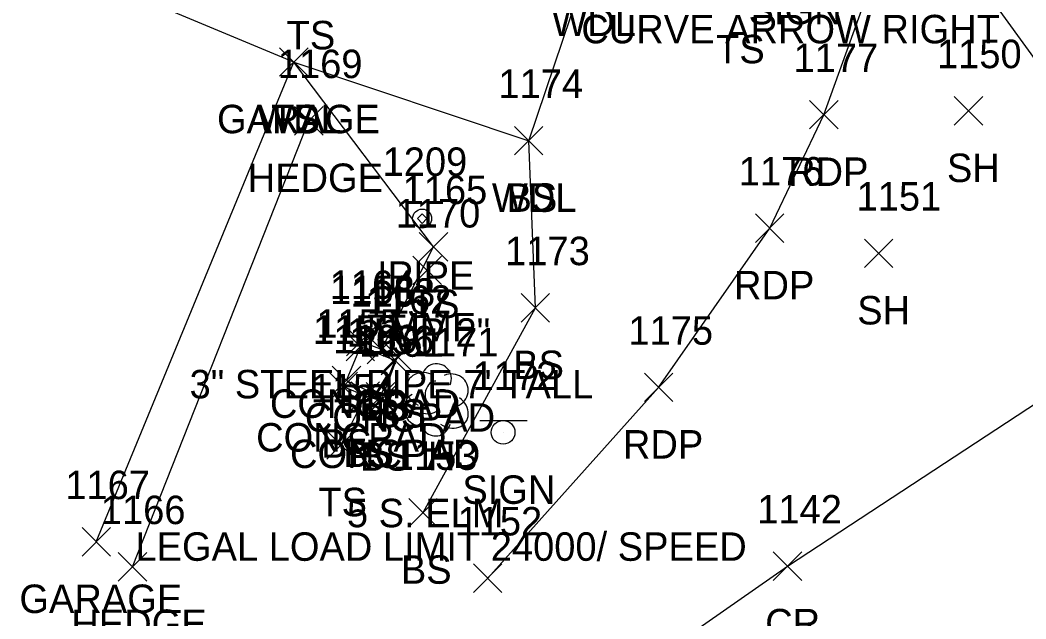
# Model space of a CAD drawing. Extents: x 1620157 to 1620595, y 115111 to 117885.
# Drawn here: x 1620292.5 to 1620363.2, y 115261.5 to 115303.5 of the extents above; entities that cross this region are included whole.
import ezdxf

# ---------------------------------------------------------------- set-up
doc = ezdxf.new("R2010")
doc.units = 0
for name, color, linetype in [('DCP', 7, 'Continuous'), ('L_A', 7, 'Continuous'), ('L_C', 7, 'Continuous'), ('L_I', 7, 'Continuous'), ('L_TIC', 7, 'Continuous'), ('LAHR', 7, 'Continuous'), ('LAWA', 7, 'Continuous'), ('LBC', 7, 'Continuous'), ('LELB', 7, 'Continuous'), ('LS', 7, 'Continuous'), ('LTD', 7, 'Continuous'), ('M_A', 7, 'Continuous'), ('M_C', 7, 'Continuous'), ('M_I', 7, 'Continuous'), ('MPIP', 7, 'Continuous'), ('P_A', 7, 'Continuous'), ('P_I', 7, 'Continuous'), ('P_TIC', 7, 'Continuous'), ('PET', 7, 'Continuous'), ('PRC', 7, 'Continuous'), ('S_A', 7, 'Continuous'), ('S_C', 7, 'Continuous'), ('S_I', 7, 'Continuous'), ('SSGN', 7, 'Continuous')]:
    doc.layers.add(name, color=color, linetype=linetype)

msp = doc.modelspace()

# ---------------------------------------------------------------- linework, layer by layer
at = {"layer": 'DCP'}
msp.add_lwpolyline([(1620401.963, 115248.346), (1620331.919, 115344.781)], dxfattribs=at)
at = {"layer": 'L_TIC'}
for points in [[(1620310.784, 115299.587), (1620312.784, 115301.587)], [(1620312.784, 115299.587), (1620310.784, 115301.587)], [(1620310.784, 115299.587), (1620312.784, 115301.587)], [(1620312.784, 115299.587), (1620310.784, 115301.587)], [(1620310.784, 115299.587), (1620312.784, 115301.587)], [(1620312.784, 115299.587), (1620310.784, 115301.587)], [(1620358.191, 115296.159), (1620360.191, 115298.159)], [(1620360.191, 115296.159), (1620358.191, 115298.159)], [(1620311.836, 115295.461), (1620313.836, 115297.461)], [(1620313.836, 115295.461), (1620311.836, 115297.461)], [(1620327.285, 115294.066), (1620329.285, 115296.066)], [(1620329.285, 115294.066), (1620327.285, 115296.066)], [(1620327.285, 115294.066), (1620329.285, 115296.066)], [(1620329.285, 115294.066), (1620327.285, 115296.066)], [(1620320.596, 115286.608), (1620322.596, 115288.608)], [(1620322.596, 115286.608), (1620320.596, 115288.608)], [(1620351.887, 115286.157), (1620353.887, 115288.157)], [(1620353.887, 115286.157), (1620351.887, 115288.157)], [(1620320.147, 115284.965), (1620322.147, 115286.965)], [(1620322.147, 115284.965), (1620320.147, 115286.965)], [(1620327.758, 115282.321), (1620329.758, 115284.321)], [(1620329.758, 115282.321), (1620327.758, 115284.321)], [(1620315.455, 115279.595), (1620317.455, 115281.595)], [(1620317.455, 115279.595), (1620315.455, 115281.595)], [(1620315.455, 115279.595), (1620317.455, 115281.595)], [(1620317.455, 115279.595), (1620315.455, 115281.595)], [(1620315.47, 115279.948), (1620317.47, 115281.948)], [(1620317.47, 115279.948), (1620315.47, 115281.948)], [(1620316.94, 115279.402), (1620318.94, 115281.402)], [(1620318.94, 115279.402), (1620316.94, 115281.402)], [(1620316.94, 115279.402), (1620318.94, 115281.402)], [(1620318.94, 115279.402), (1620316.94, 115281.402)], [(1620318.075, 115278.906), (1620320.075, 115280.906)], [(1620320.075, 115278.906), (1620318.075, 115280.906)], [(1620317.909, 115278.626), (1620319.909, 115280.626)], [(1620319.909, 115278.626), (1620317.909, 115280.626)], [(1620314.255, 115276.794), (1620316.255, 115278.794)], [(1620316.255, 115276.794), (1620314.255, 115278.794)], [(1620314.483, 115277.23), (1620316.483, 115279.23)], [(1620316.483, 115277.23), (1620314.483, 115279.23)], [(1620314.483, 115277.23), (1620316.483, 115279.23)], [(1620316.483, 115277.23), (1620314.483, 115279.23)], [(1620315.807, 115276.134), (1620317.807, 115278.134)], [(1620317.807, 115276.134), (1620315.807, 115278.134)], [(1620315.807, 115276.134), (1620317.807, 115278.134)], [(1620317.807, 115276.134), (1620315.807, 115278.134)], [(1620316.868, 115276.07), (1620318.868, 115278.07)], [(1620318.868, 115276.07), (1620316.868, 115278.07)], [(1620316.97, 115275.884), (1620318.97, 115277.884)], [(1620318.97, 115275.884), (1620316.97, 115277.884)], [(1620314.093, 115272.686), (1620316.093, 115274.686)], [(1620316.093, 115272.686), (1620314.093, 115274.686)], [(1620319.862, 115267.942), (1620321.862, 115269.942)], [(1620321.862, 115267.942), (1620319.862, 115269.942)], [(1620296.895, 115265.887), (1620298.895, 115267.887)], [(1620298.895, 115265.887), (1620296.895, 115267.887)], [(1620299.443, 115264.132), (1620301.443, 115266.132)], [(1620301.443, 115264.132), (1620299.443, 115266.132)]]:
    msp.add_lwpolyline(points, dxfattribs=at)
at = {"layer": 'LAHR'}
msp.add_lwpolyline([(1620300.443, 115265.132), (1620312.836, 115296.461)], dxfattribs=at)
at = {"layer": 'LAWA'}
msp.add_lwpolyline([(1620311.784, 115300.587), (1620328.285, 115295.066), (1620332.468, 115307.412), (1620334.855, 115331.074), (1620331.839, 115338.897)], dxfattribs=at)
at = {"layer": 'LBC'}
msp.add_lwpolyline([(1620297.895, 115266.887), (1620311.784, 115300.587), (1620292.544, 115308.613)], dxfattribs=at)
at = {"layer": 'LELB'}
for points in [[(1620317.94, 115280.402), (1620321.596, 115287.608), (1620311.784, 115300.587)], [(1620320.862, 115268.942), (1620328.758, 115283.321), (1620328.285, 115295.066)], [(1620315.255, 115277.794), (1620316.807, 115277.134), (1620317.97, 115276.884), (1620319.075, 115279.906), (1620317.94, 115280.402), (1620316.47, 115280.948)], [(1620315.093, 115273.686), (1620316.807, 115277.134)]]:
    msp.add_lwpolyline(points, dxfattribs=at)
at = {"layer": 'LS'}
for points in [[(1620315.483, 115278.23), (1620317.868, 115277.07), (1620318.909, 115279.626), (1620316.455, 115280.595)], [(1620315.483, 115278.23), (1620316.455, 115280.595)]]:
    msp.add_lwpolyline(points, dxfattribs=at)
at = {"layer": 'LTD'}
msp.add_line((1620321.762, 115276.912), (1620321.762, 115276.912), dxfattribs=at)
msp.add_line((1620321.762, 115276.912), (1620321.762, 115276.912), dxfattribs=at)
msp.add_arc((1620321.809, 115278.346), 1.047, 335.52715, 180.95627, dxfattribs=at)
for centre, major_axis, ratio, start_param, end_param in [((1620320.971, 115277.579), (1.21, -0.512), 0.895232, 1.570796, 4.712389), ((1620322.804, 115277.496), (-1.141, -0.483), 0.949671, 1.570796, 4.712389), ((1620321.554, 115277.371), (-0.208, -0.792), 0.645439, 3.141593, 6.283185), ((1620322.262, 115276.746), (-0.5, 0.667), 0.989748, 3.141593, 6.283185), ((1620320.679, 115276.204), (0.584, -1.042), 0.959034, 3.141593, 6.283185), ((1620322.762, 115276.079), (-1.09, 0.792), 0.841452, 1.570796, 4.712389), ((1620321.304, 115276.162), (-0.625, -0.083), 0.423636, 0, 3.141593), ((1620321.763, 115275.412), (0.265, 1.061), 0.942809, 1.570796, 4.712389)]:
    msp.add_ellipse(centre, major_axis=major_axis, ratio=ratio, start_param=start_param, end_param=end_param, dxfattribs=at)
at = {"layer": 'MPIP'}
msp.add_lwpolyline([(1620321.131, 115289.591), (1620320.797, 115289.925), (1620320.464, 115289.591), (1620320.797, 115289.258)], close=True, dxfattribs=at)
msp.add_circle((1620320.797, 115289.591), 0.667, dxfattribs=at)
at = {"layer": 'P_TIC'}
for points in [[(1620348.026, 115295.888), (1620350.026, 115297.888)], [(1620350.026, 115295.888), (1620348.026, 115297.888)], [(1620344.225, 115287.919), (1620346.225, 115289.919)], [(1620346.225, 115287.919), (1620344.225, 115289.919)], [(1620336.417, 115276.734), (1620338.417, 115278.734)], [(1620338.417, 115276.734), (1620336.417, 115278.734)], [(1620345.474, 115264.176), (1620347.474, 115266.176)], [(1620347.474, 115264.176), (1620345.474, 115266.176)], [(1620324.409, 115263.335), (1620326.409, 115265.335)], [(1620326.409, 115263.335), (1620324.409, 115265.335)]]:
    msp.add_lwpolyline(points, dxfattribs=at)
at = {"layer": 'PET'}
msp.add_lwpolyline([(1620325.409, 115264.335), (1620337.417, 115277.734), (1620345.225, 115288.919), (1620349.026, 115296.888), (1620353.56, 115309.423), (1620355.676, 115318.837), (1620356.593, 115324.555)], dxfattribs=at)
at = {"layer": 'PRC'}
msp.add_lwpolyline([(1620331.978, 115255.064), (1620346.474, 115265.176), (1620365.552, 115277.691), (1620370.361, 115280.843), (1620377.45, 115285.521), (1620380.209, 115287.874)], dxfattribs=at)
at = {"layer": 'SSGN'}
for p, q in [((1620324.84, 115275.409), (1620328.173, 115275.409)), ((1620326.486, 115274.576), (1620326.486, 115274.576))]:
    msp.add_line(p, q, dxfattribs=at)
msp.add_circle((1620326.486, 115274.576), 0.833, dxfattribs=at)

# ---------------------------------------------------------------- texts
at = {"layer": 'L_A'}
for s, p in [('WDL', (1620329.885, 115302.412)), ('TS', (1620311.274, 115301.479)), ('TS', (1620341.457, 115300.499)), ('GARAGE', (1620306.383, 115295.587)), ('WDL', (1620309.201, 115295.587)), ('TS', (1620310.194, 115295.587)), ('SH', (1620357.679, 115292.159)), ('HEDGE', (1620308.537, 115291.461)), ('WDL', (1620325.702, 115290.066)), ('BS', (1620326.726, 115290.066)), ('TS', (1620320.006, 115282.608)), ('SH', (1620351.375, 115282.157)), ('MMF', (1620318.43, 115280.965)), ('BS', (1620327.199, 115278.321)), ('CONCPAD', (1620310.101, 115275.595)), ('CONCPAD', (1620310.101, 115275.595)), ('BS', (1620314.911, 115275.948)), ('TS', (1620316.35, 115275.402)), ('BS', (1620316.381, 115275.402)), ('CONCPAD', (1620312.554, 115274.626)), ('BS', (1620317.516, 115274.906)), ('CONCPAD', (1620309.129, 115273.23)), ('CONCPAD', (1620309.129, 115273.23)), ('BS', (1620313.696, 115272.794)), ('CONCPAD', (1620311.513, 115272.07)), ('TS', (1620315.216, 115272.134)), ('BS', (1620315.248, 115272.134)), ('BS', (1620316.411, 115271.884)), ('H', (1620321.195, 115271.912)), ('TS', (1620313.503, 115268.686)), ('BS', (1620319.303, 115263.942)), ('GARAGE', (1620292.493, 115261.887)), ('HEDGE', (1620296.144, 115260.132))]:
    msp.add_text(s, height=2, dxfattribs=at).set_placement(p)
at = {"layer": 'L_C'}
for s, p in [('3" STEEL PIPE 7\' TALL', (1620304.455, 115276.965)), ('5 S. ELM', (1620315.51, 115267.912))]:
    msp.add_text(s, height=2, dxfattribs=at).set_placement(p)
at = {"layer": 'L_I'}
for s, p in [('1150', (1620356.979, 115300.159)), ('1169', (1620310.655, 115299.461)), ('1174', (1620326.159, 115298.066)), ('1174', (1620326.159, 115298.066)), ('1165', (1620319.423, 115290.608)), ('1151', (1620351.328, 115290.157)), ('1170', (1620318.935, 115288.965)), ('1173', (1620326.632, 115286.321)), ('1164', (1620314.297, 115283.948)), ('1158', (1620314.329, 115283.595)), ('1158', (1620314.329, 115283.595)), ('1163', (1620315.767, 115283.402)), ('1163', (1620315.767, 115283.402)), ('1157', (1620316.783, 115282.626)), ('1162', (1620316.902, 115282.906)), ('1155', (1620313.358, 115281.23)), ('1155', (1620313.358, 115281.23)), ('1159', (1620313.122, 115280.794)), ('1160', (1620314.547, 115280.134)), ('1160', (1620314.547, 115280.134)), ('1156', (1620315.687, 115280.07)), ('1161', (1620316.364, 115279.884)), ('1171', (1620320.204, 115279.912)), ('1154', (1620312.968, 115276.686)), ('1153', (1620318.737, 115271.942)), ('1167', (1620295.722, 115269.887)), ('1166', (1620298.215, 115268.132))]:
    msp.add_text(s, height=2, dxfattribs=at).set_placement(p)
at = {"layer": 'M_A'}
msp.add_text('IPIPE', height=2, dxfattribs=at).set_placement((1620317.632, 115284.591))
at = {"layer": 'M_C'}
msp.add_text('1" UP 2"', height=2, dxfattribs=at).set_placement((1620315.506, 115280.591))
at = {"layer": 'M_I'}
msp.add_text('1209', height=2, dxfattribs=at).set_placement((1620318.018, 115292.591))
at = {"layer": 'P_A'}
for s, p in [('RDP', (1620346.514, 115291.888)), ('RDP', (1620342.713, 115283.919)), ('RDP', (1620334.906, 115272.734)), ('CR', (1620344.907, 115260.176))]:
    msp.add_text(s, height=2, dxfattribs=at).set_placement(p)
at = {"layer": 'P_I'}
for s, p in [('1177', (1620346.9, 115299.888)), ('1176', (1620343.044, 115291.919)), ('1175', (1620335.292, 115280.734)), ('1142', (1620344.348, 115268.176)), ('1152', (1620323.283, 115267.335))]:
    msp.add_text(s, height=2, dxfattribs=at).set_placement(p)
at = {"layer": 'S_A'}
for p in [(1620343.74, 115303.24), (1620323.624, 115269.555)]:
    msp.add_text('SIGN', height=2, dxfattribs=at).set_placement(p)
at = {"layer": 'S_C'}
for s, p in [('CURVE ARROW RIGHT', (1620331.982, 115301.903)), ('LEGAL LOAD LIMIT 24000/ SPEED', (1620300.649, 115265.555))]:
    msp.add_text(s, height=2, dxfattribs=at).set_placement(p)
at = {"layer": 'S_I'}
msp.add_text('1172', height=2, dxfattribs=at).set_placement((1620324.341, 115277.555))

doc.saveas('drawing.dxf')
